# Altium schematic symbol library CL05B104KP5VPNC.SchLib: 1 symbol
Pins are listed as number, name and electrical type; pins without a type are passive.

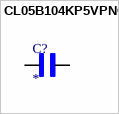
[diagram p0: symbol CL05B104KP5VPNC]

## CL05B104KP5VPNC
designator C?
0.1 ÂµF Â±10% 10V Ceramic Capacitor X7R 0402 (1005 Metric); MF: Samsung; MP: CL05B104KP5VPNC
footprint CAPC1005X55N
pins: 1, 2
